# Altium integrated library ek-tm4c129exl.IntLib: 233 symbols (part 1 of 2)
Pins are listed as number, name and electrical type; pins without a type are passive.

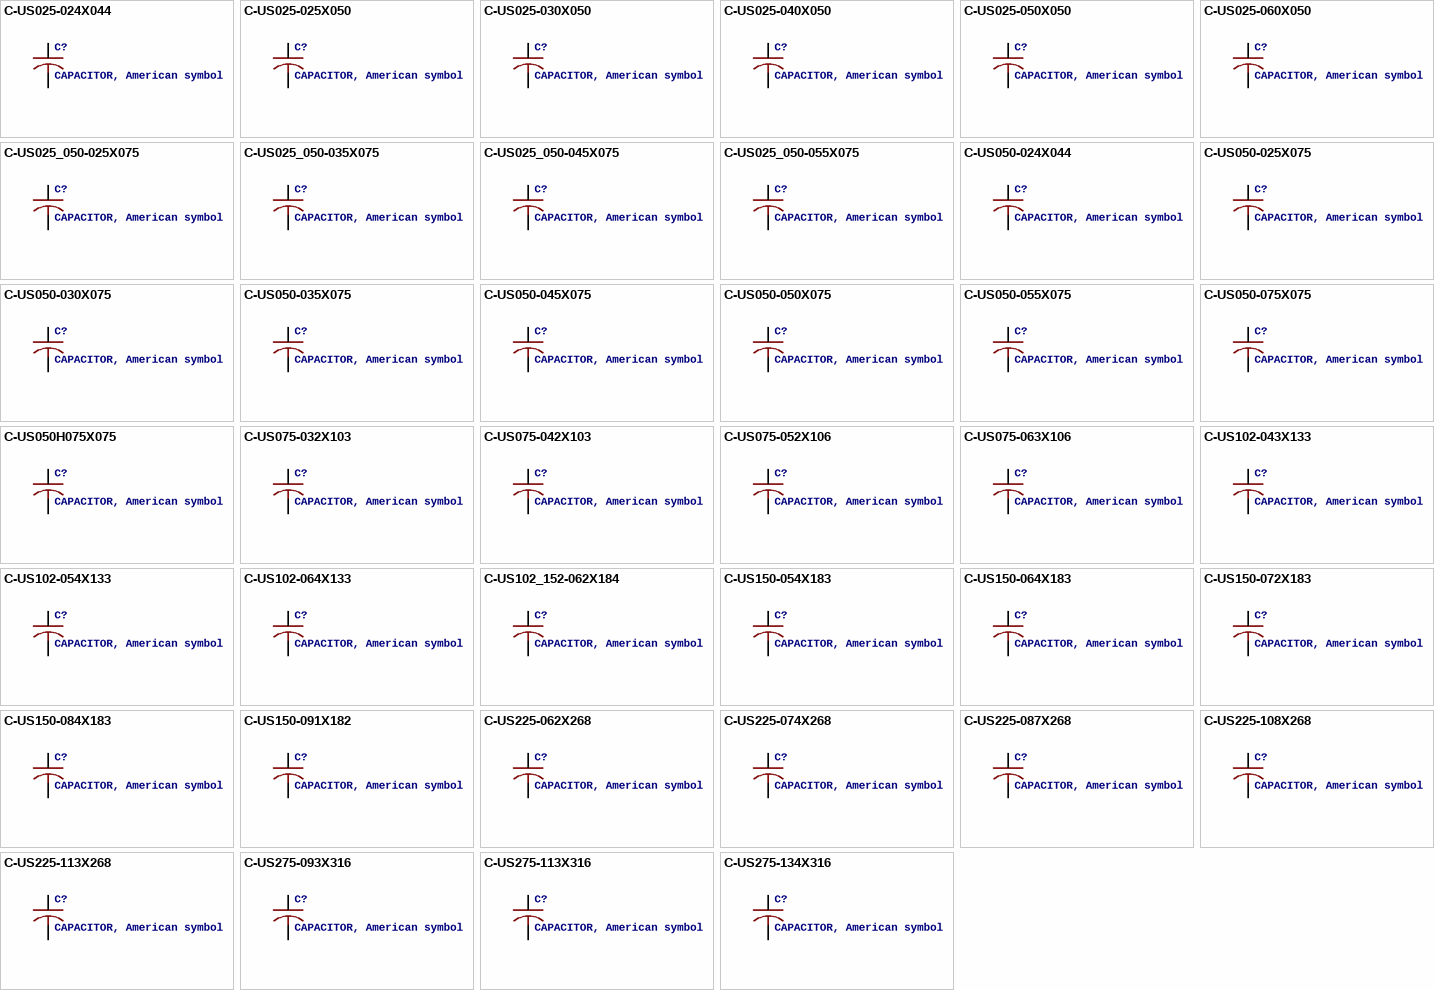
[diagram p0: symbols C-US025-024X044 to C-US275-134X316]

## C-US025-024X044
designator C?, comment CAPACITOR, American symbol
footprint C025-024X044
pins: 1, 2

## C-US025-025X050
designator C?, comment CAPACITOR, American symbol
footprint C025-025X050
pins: 1, 2

## C-US025-030X050
designator C?, comment CAPACITOR, American symbol
footprint C025-030X050
pins: 1, 2

## C-US025-040X050
designator C?, comment CAPACITOR, American symbol
footprint C025-040X050
pins: 1, 2

## C-US025-050X050
designator C?, comment CAPACITOR, American symbol
footprint C025-050X050
pins: 1, 2

## C-US025-060X050
designator C?, comment CAPACITOR, American symbol
footprint C025-060X050
pins: 1, 2

## C-US025_050-025X075
designator C?, comment CAPACITOR, American symbol
footprint C025_050-025X075
pins: 1, 2

## C-US025_050-035X075
designator C?, comment CAPACITOR, American symbol
footprint C025_050-035X075
pins: 1, 2

## C-US025_050-045X075
designator C?, comment CAPACITOR, American symbol
footprint C025_050-045X075
pins: 1, 2

## C-US025_050-055X075
designator C?, comment CAPACITOR, American symbol
footprint C025_050-055X075
pins: 1, 2

## C-US050-024X044
designator C?, comment CAPACITOR, American symbol
footprint C050-024X044
pins: 1, 2

## C-US050-025X075
designator C?, comment CAPACITOR, American symbol
footprint C050-025X075
pins: 1, 2

## C-US050-030X075
designator C?, comment CAPACITOR, American symbol
footprint C050-030X075
pins: 1, 2

## C-US050-035X075
designator C?, comment CAPACITOR, American symbol
footprint C050-035X075
pins: 1, 2

## C-US050-045X075
designator C?, comment CAPACITOR, American symbol
footprint C050-045X075
pins: 1, 2

## C-US050-050X075
designator C?, comment CAPACITOR, American symbol
footprint C050-050X075
pins: 1, 2

## C-US050-055X075
designator C?, comment CAPACITOR, American symbol
footprint C050-055X075
pins: 1, 2

## C-US050-075X075
designator C?, comment CAPACITOR, American symbol
footprint C050-075X075
pins: 1, 2

## C-US050H075X075
designator C?, comment CAPACITOR, American symbol
footprint C050H075X075
pins: 1, 2

## C-US075-032X103
designator C?, comment CAPACITOR, American symbol
footprint C075-032X103
pins: 1, 2

## C-US075-042X103
designator C?, comment CAPACITOR, American symbol
footprint C075-042X103
pins: 1, 2

## C-US075-052X106
designator C?, comment CAPACITOR, American symbol
footprint C075-052X106
pins: 1, 2

## C-US075-063X106
designator C?, comment CAPACITOR, American symbol
footprint C075-063X106
pins: 1, 2

## C-US102-043X133
designator C?, comment CAPACITOR, American symbol
footprint C102-043X133
pins: 1, 2

## C-US102-054X133
designator C?, comment CAPACITOR, American symbol
footprint C102-054X133
pins: 1, 2

## C-US102-064X133
designator C?, comment CAPACITOR, American symbol
footprint C102-064X133
pins: 1, 2

## C-US102_152-062X184
designator C?, comment CAPACITOR, American symbol
footprint C102_152-062X184
pins: 1, 2

## C-US150-054X183
designator C?, comment CAPACITOR, American symbol
footprint C150-054X183
pins: 1, 2

## C-US150-064X183
designator C?, comment CAPACITOR, American symbol
footprint C150-064X183
pins: 1, 2

## C-US150-072X183
designator C?, comment CAPACITOR, American symbol
footprint C150-072X183
pins: 1, 2

## C-US150-084X183
designator C?, comment CAPACITOR, American symbol
footprint C150-084X183
pins: 1, 2

## C-US150-091X182
designator C?, comment CAPACITOR, American symbol
footprint C150-091X182
pins: 1, 2

## C-US225-062X268
designator C?, comment CAPACITOR, American symbol
footprint C225-062X268
pins: 1, 2

## C-US225-074X268
designator C?, comment CAPACITOR, American symbol
footprint C225-074X268
pins: 1, 2

## C-US225-087X268
designator C?, comment CAPACITOR, American symbol
footprint C225-087X268
pins: 1, 2

## C-US225-108X268
designator C?, comment CAPACITOR, American symbol
footprint C225-108X268
pins: 1, 2

## C-US225-113X268
designator C?, comment CAPACITOR, American symbol
footprint C225-113X268
pins: 1, 2

## C-US275-093X316
designator C?, comment CAPACITOR, American symbol
footprint C275-093X316
pins: 1, 2

## C-US275-113X316
designator C?, comment CAPACITOR, American symbol
footprint C275-113X316
pins: 1, 2

## C-US275-134X316
designator C?, comment CAPACITOR, American symbol
footprint C275-134X316
pins: 1, 2

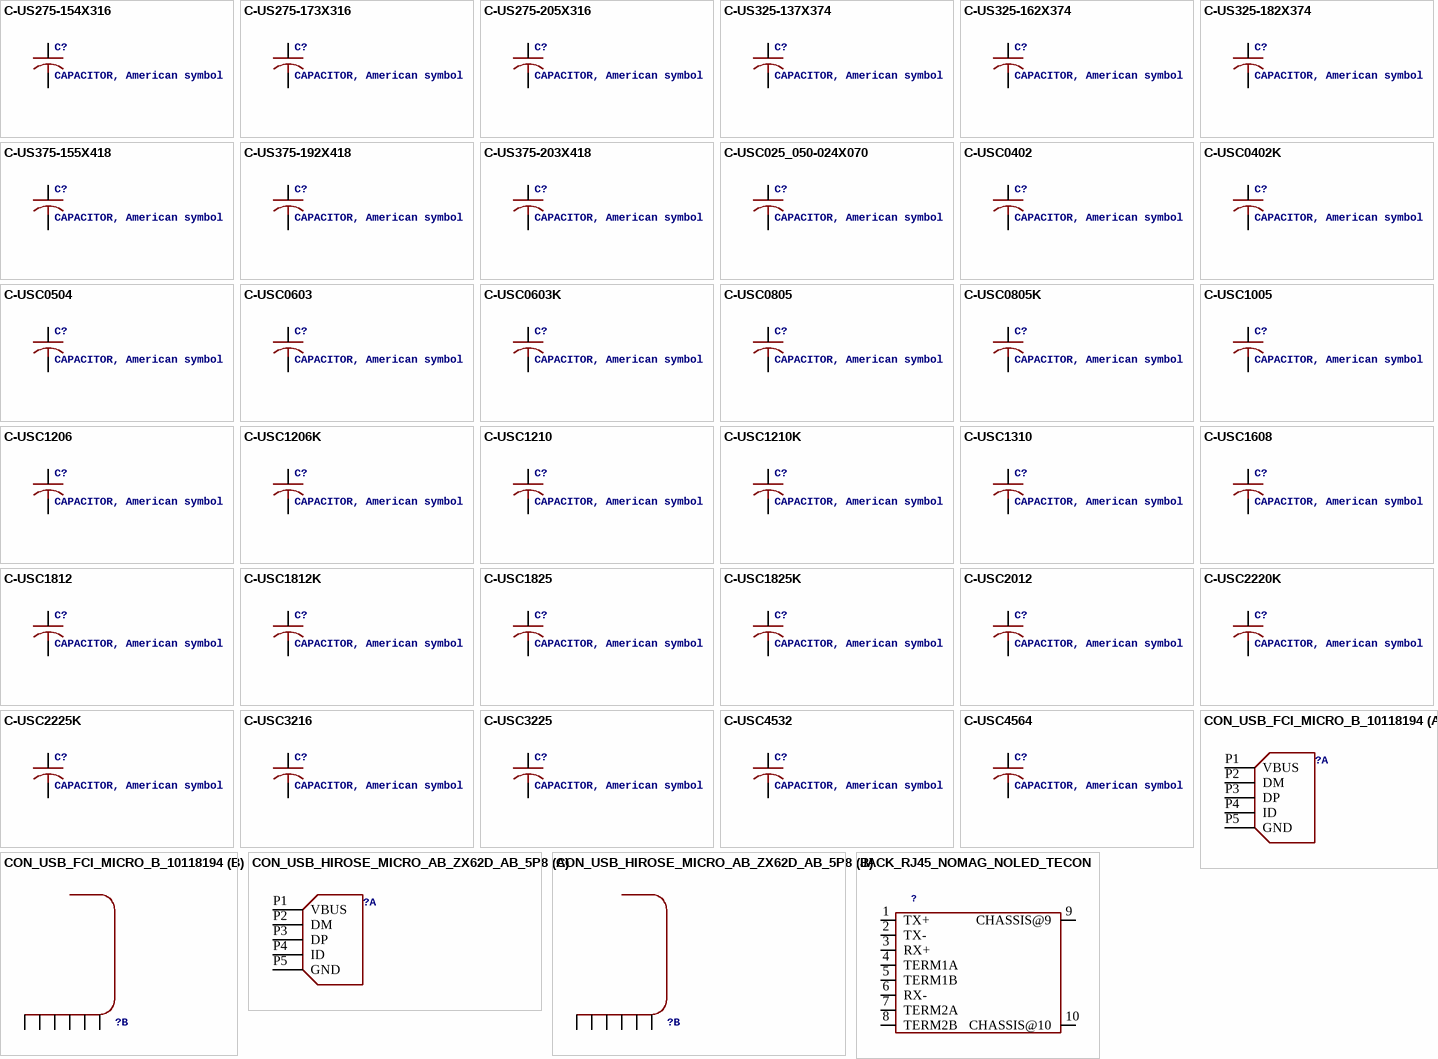
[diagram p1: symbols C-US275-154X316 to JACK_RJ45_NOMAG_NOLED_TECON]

## C-US275-154X316
designator C?, comment CAPACITOR, American symbol
footprint C275-154X316
pins: 1, 2

## C-US275-173X316
designator C?, comment CAPACITOR, American symbol
footprint C275-173X316
pins: 1, 2

## C-US275-205X316
designator C?, comment CAPACITOR, American symbol
footprint C275-205X316
pins: 1, 2

## C-US325-137X374
designator C?, comment CAPACITOR, American symbol
footprint C325-137X374
pins: 1, 2

## C-US325-162X374
designator C?, comment CAPACITOR, American symbol
footprint C325-162X374
pins: 1, 2

## C-US325-182X374
designator C?, comment CAPACITOR, American symbol
footprint C325-182X374
pins: 1, 2

## C-US375-155X418
designator C?, comment CAPACITOR, American symbol
footprint C375-155X418
pins: 1, 2

## C-US375-192X418
designator C?, comment CAPACITOR, American symbol
footprint C375-192X418
pins: 1, 2

## C-US375-203X418
designator C?, comment CAPACITOR, American symbol
footprint C375-203X418
pins: 1, 2

## C-USC025_050-024X070
designator C?, comment CAPACITOR, American symbol
footprint C025_050-024X070
pins: 1, 2

## C-USC0402
designator C?, comment CAPACITOR, American symbol
footprint C0402
pins: 1, 2

## C-USC0402K
designator C?, comment CAPACITOR, American symbol
footprint C0402K
pins: 1, 2

## C-USC0504
designator C?, comment CAPACITOR, American symbol
footprint C0504
pins: 1, 2

## C-USC0603
designator C?, comment CAPACITOR, American symbol
footprint C0603
pins: 1, 2

## C-USC0603K
designator C?, comment CAPACITOR, American symbol
footprint C0603K
pins: 1, 2

## C-USC0805
designator C?, comment CAPACITOR, American symbol
footprint C0805
pins: 1, 2

## C-USC0805K
designator C?, comment CAPACITOR, American symbol
footprint C0805K
pins: 1, 2

## C-USC1005
designator C?, comment CAPACITOR, American symbol
footprint C1005
pins: 1, 2

## C-USC1206
designator C?, comment CAPACITOR, American symbol
footprint C1206
pins: 1, 2

## C-USC1206K
designator C?, comment CAPACITOR, American symbol
footprint C1206K
pins: 1, 2

## C-USC1210
designator C?, comment CAPACITOR, American symbol
footprint C1210
pins: 1, 2

## C-USC1210K
designator C?, comment CAPACITOR, American symbol
footprint C1210K
pins: 1, 2

## C-USC1310
designator C?, comment CAPACITOR, American symbol
footprint C1310
pins: 1, 2

## C-USC1608
designator C?, comment CAPACITOR, American symbol
footprint C1608
pins: 1, 2

## C-USC1812
designator C?, comment CAPACITOR, American symbol
footprint C1812
pins: 1, 2

## C-USC1812K
designator C?, comment CAPACITOR, American symbol
footprint C1812K
pins: 1, 2

## C-USC1825
designator C?, comment CAPACITOR, American symbol
footprint C1825
pins: 1, 2

## C-USC1825K
designator C?, comment CAPACITOR, American symbol
footprint C1825K
pins: 1, 2

## C-USC2012
designator C?, comment CAPACITOR, American symbol
footprint C2012
pins: 1, 2

## C-USC2220K
designator C?, comment CAPACITOR, American symbol
footprint C2220K
pins: 1, 2

## C-USC2225K
designator C?, comment CAPACITOR, American symbol
footprint C2225K
pins: 1, 2

## C-USC3216
designator C?, comment CAPACITOR, American symbol
footprint C3216
pins: 1, 2

## C-USC3225
designator C?, comment CAPACITOR, American symbol
footprint C3225
pins: 1, 2

## C-USC4532
designator C?, comment CAPACITOR, American symbol
footprint C4532
pins: 1, 2

## C-USC4564
designator C?, comment CAPACITOR, American symbol
footprint C4564
pins: 1, 2

## CON_USB_FCI_MICRO_B_10118194
designator ?
footprint CON_USB_MICRO_B_FCI_10118194
part A pins: P1 VBUS, P2 DM, P3 DP, P4 ID, P5 GND
part B pins: P6 S1, P7 S2, P8 S3, P9 S4, P10 S5, P11 S6

## CON_USB_HIROSE_MICRO_AB_ZX62D_AB_5P8
designator ?
footprint CON_USB_MICRO_AB_HIROSE_ZX62D-AB-5P8
part A pins: P1 VBUS, P2 DM, P3 DP, P4 ID, P5 GND
part B pins: P$1 S1, P$2 S2, P$3 S3, P$4 S4, P$5 S5, P$6 S6

## JACK_RJ45_NOMAG_NOLED_TECON
designator ?
footprint RJ45_TE_CON_NOMAG_NOLED
pins: 1 TX+, 2 TX-, 3 RX+, 4 TERM1A, 5 TERM1B, 6 RX-, 7 TERM2A, 8 TERM2B, 9 CHASSIS@9, 10 CHASSIS@10

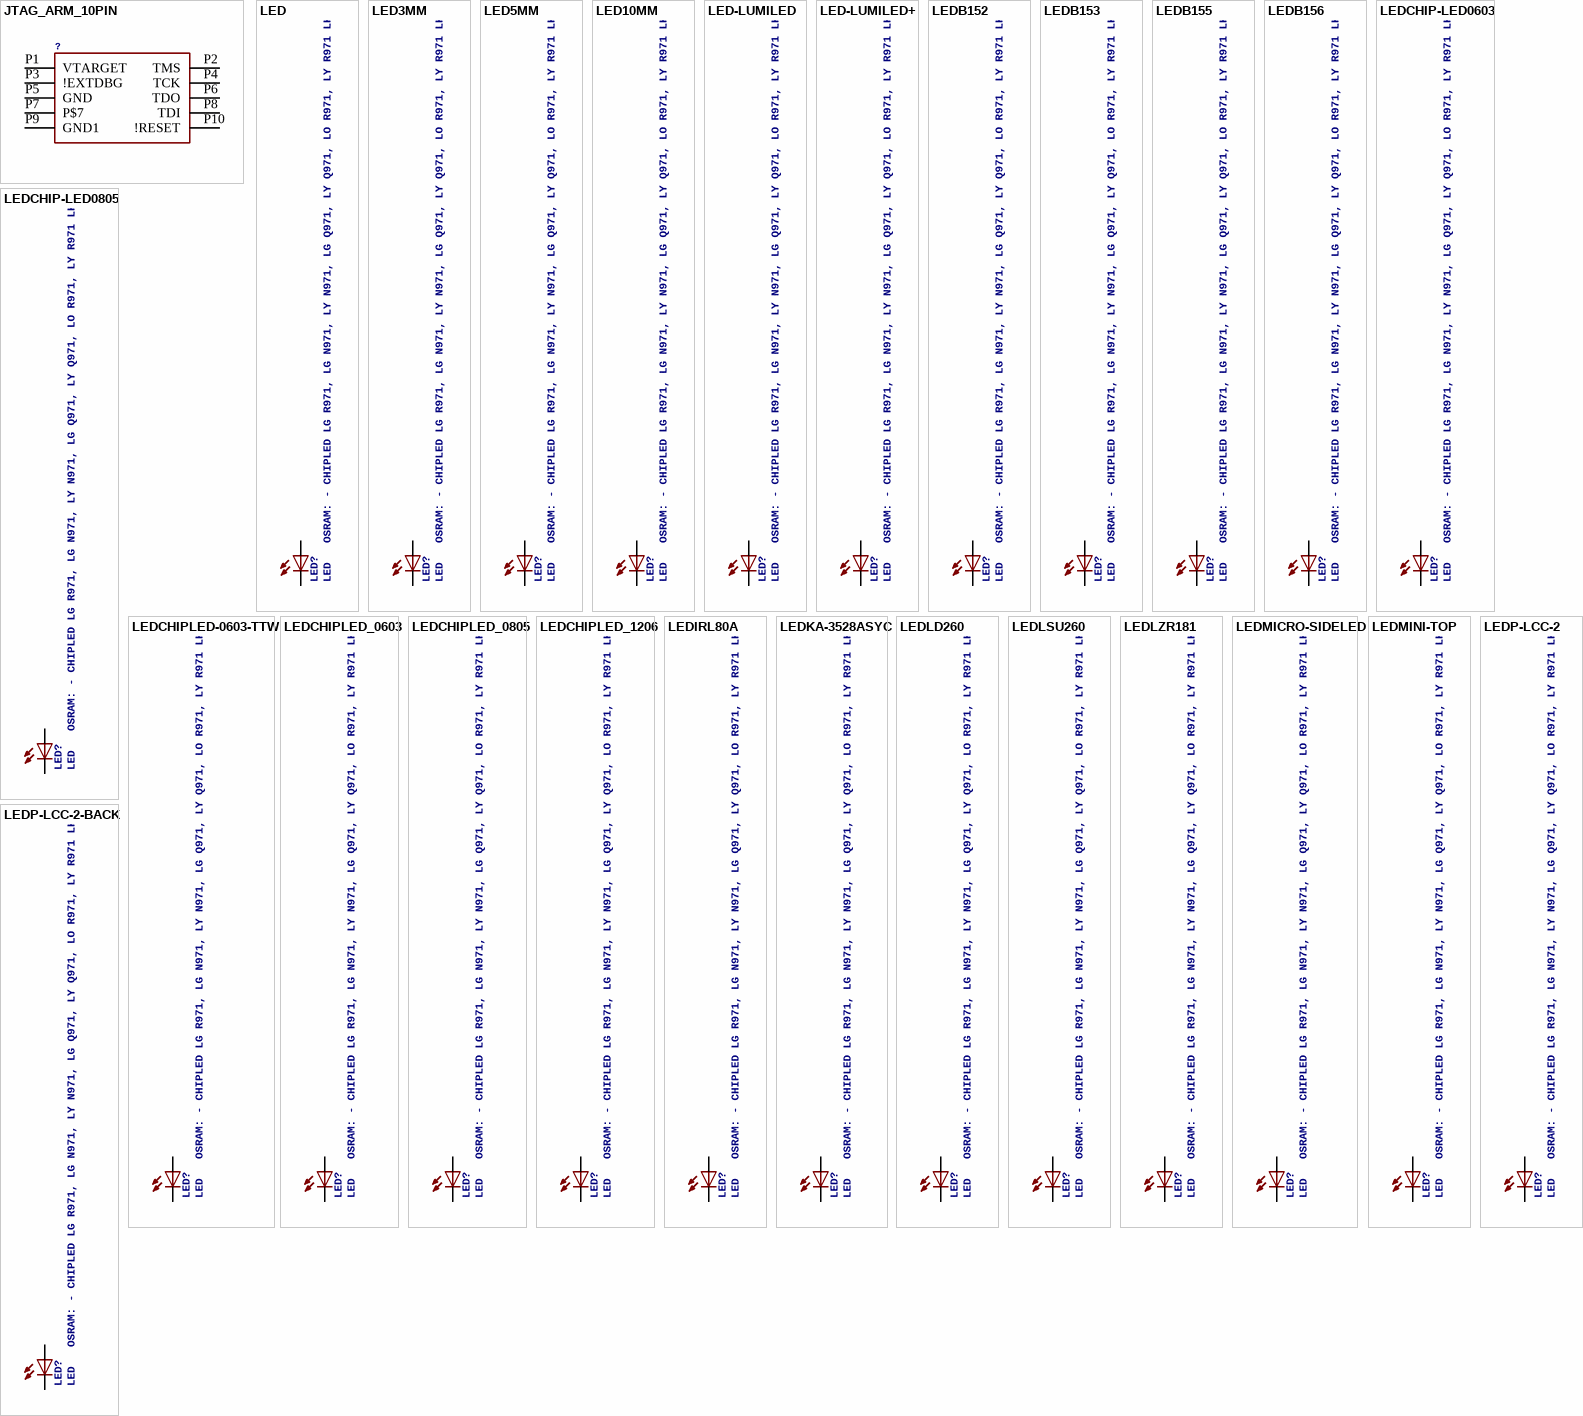
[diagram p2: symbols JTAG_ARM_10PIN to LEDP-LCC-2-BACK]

## JTAG_ARM_10PIN
designator ?
footprint CON_2X5_50MIL
pins: P1 VTARGET, P2 TMS, P3 !EXTDBG, P4 TCK, P5 GND, P6 TDO, P7 P$7, P8 TDI, P9 GND1, P10 !RESET

## LED
designator LED?, comment LED   OSRAM: - CHIPLED LG R971, LG N971, LY N971, LG Q971, LY Q971, LO R971, LY R971 LH N974, LH R974 LS Q976, LO Q976, LY Q976 LO Q996 - Hyper CHIPLED LW Q18S LB Q993, LB Q99A, LB R99A - SideLED LS A670, LO A670, LY A670, LG A670, LP A670 LB A673, LV A673, LT A673, LW A673 LH A674 LY A675 LS A676, LA A676, LO A676, LY A676, LW A676 LS A679, LY A679, LG A679 -  Hyper Micro SIDELEDÂ® LS Y876, LA Y876, LO Y876, LY Y876 LT Y87S - SmartLED LW L88C, LW L88S LB L89C, LB L89S, LG L890 LS L89K, LO L89K, LY L89K LS L896, LA L896, LO L896, LY L896 - TOPLED LS T670, LO T670, LY T670, LG T670, LP T670 LSG T670, LSP T670, LSY T670, LOP T670, LYG T670 LG T671, LOG T671, LSG T671 LB T673, LV T673, LT T673, LW T673 LH T674 LS T676, LA T676, LO T676, LY T676, LB T676, LH T676, LSB T676, LW T676 LB T67C, LV T67C, LT T67C, LS T67K, LO T67K, LY T67K, LW E67C LS E67B, LA E67B, LO E67B, LY E67B, LB E67C, LV E67C, LT E67C LW T67C LS T679, LY T679, LG T679 LS T770, LO T770, LY T770, LG T770, LP T770 LB T773, LV T773, LT T773, LW T773 LH T774 LS E675, LA E675, LY E675, LS T675 LS T776, LA T776, LO T776, LY T776, LB T776 LHGB T686 LT T68C, LB T68C - Hyper Mini TOPLEDÂ® LB M676 - Mini TOPLED SantanaÂ® LG M470 LS M47K, LO M47K, LY M47K    Source: http://www.osram.convergy.de   LUXEON: - LUMILEDÂ® LXK2-PW12-R00, LXK2-PW12-S00, LXK2-PW14-U00, LXK2-PW14-V00 LXK2-PM12-R00, LXK2-PM12-S00, LXK2-PM14-U00 LXK2-PE12-Q00, LXK2-PE12-R00, LXK2-PE12-S00, LXK2-PE14-T00, LXK2-PE14-U00 LXK2-PB12-K00, LXK2-PB12-L00, LXK2-PB12-M00, LXK2-PB14-N00, LXK2-PB14-P00, LXK2-PB14-Q00 LXK2-PR12-L00, LXK2-PR12-M00, LXK2-PR14-Q00, LXK2-PR14-R00 LXK2-PD12-Q00, LXK2-PD12-R00, LXK2-PD12-S00 LXK2-PH12-R00, LXK2-PH12-S00 LXK2-PL12-P00, LXK2-PL12-Q00, LXK2-PL12-R00    Source: www.luxeon.com   KINGBRIGHT:   KA-3528ASYC Source: www.kingbright.com
footprint SMARTLED-TTW
pins: A@1 A, C@1 C

## LED3MM
designator LED?, comment LED   OSRAM: - CHIPLED LG R971, LG N971, LY N971, LG Q971, LY Q971, LO R971, LY R971 LH N974, LH R974 LS Q976, LO Q976, LY Q976 LO Q996 - Hyper CHIPLED LW Q18S LB Q993, LB Q99A, LB R99A - SideLED LS A670, LO A670, LY A670, LG A670, LP A670 LB A673, LV A673, LT A673, LW A673 LH A674 LY A675 LS A676, LA A676, LO A676, LY A676, LW A676 LS A679, LY A679, LG A679 -  Hyper Micro SIDELEDÂ® LS Y876, LA Y876, LO Y876, LY Y876 LT Y87S - SmartLED LW L88C, LW L88S LB L89C, LB L89S, LG L890 LS L89K, LO L89K, LY L89K LS L896, LA L896, LO L896, LY L896 - TOPLED LS T670, LO T670, LY T670, LG T670, LP T670 LSG T670, LSP T670, LSY T670, LOP T670, LYG T670 LG T671, LOG T671, LSG T671 LB T673, LV T673, LT T673, LW T673 LH T674 LS T676, LA T676, LO T676, LY T676, LB T676, LH T676, LSB T676, LW T676 LB T67C, LV T67C, LT T67C, LS T67K, LO T67K, LY T67K, LW E67C LS E67B, LA E67B, LO E67B, LY E67B, LB E67C, LV E67C, LT E67C LW T67C LS T679, LY T679, LG T679 LS T770, LO T770, LY T770, LG T770, LP T770 LB T773, LV T773, LT T773, LW T773 LH T774 LS E675, LA E675, LY E675, LS T675 LS T776, LA T776, LO T776, LY T776, LB T776 LHGB T686 LT T68C, LB T68C - Hyper Mini TOPLEDÂ® LB M676 - Mini TOPLED SantanaÂ® LG M470 LS M47K, LO M47K, LY M47K    Source: http://www.osram.convergy.de   LUXEON: - LUMILEDÂ® LXK2-PW12-R00, LXK2-PW12-S00, LXK2-PW14-U00, LXK2-PW14-V00 LXK2-PM12-R00, LXK2-PM12-S00, LXK2-PM14-U00 LXK2-PE12-Q00, LXK2-PE12-R00, LXK2-PE12-S00, LXK2-PE14-T00, LXK2-PE14-U00 LXK2-PB12-K00, LXK2-PB12-L00, LXK2-PB12-M00, LXK2-PB14-N00, LXK2-PB14-P00, LXK2-PB14-Q00 LXK2-PR12-L00, LXK2-PR12-M00, LXK2-PR14-Q00, LXK2-PR14-R00 LXK2-PD12-Q00, LXK2-PD12-R00, LXK2-PD12-S00 LXK2-PH12-R00, LXK2-PH12-S00 LXK2-PL12-P00, LXK2-PL12-Q00, LXK2-PL12-R00    Source: www.luxeon.com   KINGBRIGHT:   KA-3528ASYC Source: www.kingbright.com
footprint LED3MM
pins: A, K C

## LED5MM
designator LED?, comment LED   OSRAM: - CHIPLED LG R971, LG N971, LY N971, LG Q971, LY Q971, LO R971, LY R971 LH N974, LH R974 LS Q976, LO Q976, LY Q976 LO Q996 - Hyper CHIPLED LW Q18S LB Q993, LB Q99A, LB R99A - SideLED LS A670, LO A670, LY A670, LG A670, LP A670 LB A673, LV A673, LT A673, LW A673 LH A674 LY A675 LS A676, LA A676, LO A676, LY A676, LW A676 LS A679, LY A679, LG A679 -  Hyper Micro SIDELEDÂ® LS Y876, LA Y876, LO Y876, LY Y876 LT Y87S - SmartLED LW L88C, LW L88S LB L89C, LB L89S, LG L890 LS L89K, LO L89K, LY L89K LS L896, LA L896, LO L896, LY L896 - TOPLED LS T670, LO T670, LY T670, LG T670, LP T670 LSG T670, LSP T670, LSY T670, LOP T670, LYG T670 LG T671, LOG T671, LSG T671 LB T673, LV T673, LT T673, LW T673 LH T674 LS T676, LA T676, LO T676, LY T676, LB T676, LH T676, LSB T676, LW T676 LB T67C, LV T67C, LT T67C, LS T67K, LO T67K, LY T67K, LW E67C LS E67B, LA E67B, LO E67B, LY E67B, LB E67C, LV E67C, LT E67C LW T67C LS T679, LY T679, LG T679 LS T770, LO T770, LY T770, LG T770, LP T770 LB T773, LV T773, LT T773, LW T773 LH T774 LS E675, LA E675, LY E675, LS T675 LS T776, LA T776, LO T776, LY T776, LB T776 LHGB T686 LT T68C, LB T68C - Hyper Mini TOPLEDÂ® LB M676 - Mini TOPLED SantanaÂ® LG M470 LS M47K, LO M47K, LY M47K    Source: http://www.osram.convergy.de   LUXEON: - LUMILEDÂ® LXK2-PW12-R00, LXK2-PW12-S00, LXK2-PW14-U00, LXK2-PW14-V00 LXK2-PM12-R00, LXK2-PM12-S00, LXK2-PM14-U00 LXK2-PE12-Q00, LXK2-PE12-R00, LXK2-PE12-S00, LXK2-PE14-T00, LXK2-PE14-U00 LXK2-PB12-K00, LXK2-PB12-L00, LXK2-PB12-M00, LXK2-PB14-N00, LXK2-PB14-P00, LXK2-PB14-Q00 LXK2-PR12-L00, LXK2-PR12-M00, LXK2-PR14-Q00, LXK2-PR14-R00 LXK2-PD12-Q00, LXK2-PD12-R00, LXK2-PD12-S00 LXK2-PH12-R00, LXK2-PH12-S00 LXK2-PL12-P00, LXK2-PL12-Q00, LXK2-PL12-R00    Source: www.luxeon.com   KINGBRIGHT:   KA-3528ASYC Source: www.kingbright.com
footprint LED5MM
pins: A, K C

## LED10MM
designator LED?, comment LED   OSRAM: - CHIPLED LG R971, LG N971, LY N971, LG Q971, LY Q971, LO R971, LY R971 LH N974, LH R974 LS Q976, LO Q976, LY Q976 LO Q996 - Hyper CHIPLED LW Q18S LB Q993, LB Q99A, LB R99A - SideLED LS A670, LO A670, LY A670, LG A670, LP A670 LB A673, LV A673, LT A673, LW A673 LH A674 LY A675 LS A676, LA A676, LO A676, LY A676, LW A676 LS A679, LY A679, LG A679 -  Hyper Micro SIDELEDÂ® LS Y876, LA Y876, LO Y876, LY Y876 LT Y87S - SmartLED LW L88C, LW L88S LB L89C, LB L89S, LG L890 LS L89K, LO L89K, LY L89K LS L896, LA L896, LO L896, LY L896 - TOPLED LS T670, LO T670, LY T670, LG T670, LP T670 LSG T670, LSP T670, LSY T670, LOP T670, LYG T670 LG T671, LOG T671, LSG T671 LB T673, LV T673, LT T673, LW T673 LH T674 LS T676, LA T676, LO T676, LY T676, LB T676, LH T676, LSB T676, LW T676 LB T67C, LV T67C, LT T67C, LS T67K, LO T67K, LY T67K, LW E67C LS E67B, LA E67B, LO E67B, LY E67B, LB E67C, LV E67C, LT E67C LW T67C LS T679, LY T679, LG T679 LS T770, LO T770, LY T770, LG T770, LP T770 LB T773, LV T773, LT T773, LW T773 LH T774 LS E675, LA E675, LY E675, LS T675 LS T776, LA T776, LO T776, LY T776, LB T776 LHGB T686 LT T68C, LB T68C - Hyper Mini TOPLEDÂ® LB M676 - Mini TOPLED SantanaÂ® LG M470 LS M47K, LO M47K, LY M47K    Source: http://www.osram.convergy.de   LUXEON: - LUMILEDÂ® LXK2-PW12-R00, LXK2-PW12-S00, LXK2-PW14-U00, LXK2-PW14-V00 LXK2-PM12-R00, LXK2-PM12-S00, LXK2-PM14-U00 LXK2-PE12-Q00, LXK2-PE12-R00, LXK2-PE12-S00, LXK2-PE14-T00, LXK2-PE14-U00 LXK2-PB12-K00, LXK2-PB12-L00, LXK2-PB12-M00, LXK2-PB14-N00, LXK2-PB14-P00, LXK2-PB14-Q00 LXK2-PR12-L00, LXK2-PR12-M00, LXK2-PR14-Q00, LXK2-PR14-R00 LXK2-PD12-Q00, LXK2-PD12-R00, LXK2-PD12-S00 LXK2-PH12-R00, LXK2-PH12-S00 LXK2-PL12-P00, LXK2-PL12-Q00, LXK2-PL12-R00    Source: www.luxeon.com   KINGBRIGHT:   KA-3528ASYC Source: www.kingbright.com
footprint LED10MM
pins: A, K C

## LED-LUMILED
designator LED?, comment LED   OSRAM: - CHIPLED LG R971, LG N971, LY N971, LG Q971, LY Q971, LO R971, LY R971 LH N974, LH R974 LS Q976, LO Q976, LY Q976 LO Q996 - Hyper CHIPLED LW Q18S LB Q993, LB Q99A, LB R99A - SideLED LS A670, LO A670, LY A670, LG A670, LP A670 LB A673, LV A673, LT A673, LW A673 LH A674 LY A675 LS A676, LA A676, LO A676, LY A676, LW A676 LS A679, LY A679, LG A679 -  Hyper Micro SIDELEDÂ® LS Y876, LA Y876, LO Y876, LY Y876 LT Y87S - SmartLED LW L88C, LW L88S LB L89C, LB L89S, LG L890 LS L89K, LO L89K, LY L89K LS L896, LA L896, LO L896, LY L896 - TOPLED LS T670, LO T670, LY T670, LG T670, LP T670 LSG T670, LSP T670, LSY T670, LOP T670, LYG T670 LG T671, LOG T671, LSG T671 LB T673, LV T673, LT T673, LW T673 LH T674 LS T676, LA T676, LO T676, LY T676, LB T676, LH T676, LSB T676, LW T676 LB T67C, LV T67C, LT T67C, LS T67K, LO T67K, LY T67K, LW E67C LS E67B, LA E67B, LO E67B, LY E67B, LB E67C, LV E67C, LT E67C LW T67C LS T679, LY T679, LG T679 LS T770, LO T770, LY T770, LG T770, LP T770 LB T773, LV T773, LT T773, LW T773 LH T774 LS E675, LA E675, LY E675, LS T675 LS T776, LA T776, LO T776, LY T776, LB T776 LHGB T686 LT T68C, LB T68C - Hyper Mini TOPLEDÂ® LB M676 - Mini TOPLED SantanaÂ® LG M470 LS M47K, LO M47K, LY M47K    Source: http://www.osram.convergy.de   LUXEON: - LUMILEDÂ® LXK2-PW12-R00, LXK2-PW12-S00, LXK2-PW14-U00, LXK2-PW14-V00 LXK2-PM12-R00, LXK2-PM12-S00, LXK2-PM14-U00 LXK2-PE12-Q00, LXK2-PE12-R00, LXK2-PE12-S00, LXK2-PE14-T00, LXK2-PE14-U00 LXK2-PB12-K00, LXK2-PB12-L00, LXK2-PB12-M00, LXK2-PB14-N00, LXK2-PB14-P00, LXK2-PB14-Q00 LXK2-PR12-L00, LXK2-PR12-M00, LXK2-PR14-Q00, LXK2-PR14-R00 LXK2-PD12-Q00, LXK2-PD12-R00, LXK2-PD12-S00 LXK2-PH12-R00, LXK2-PH12-S00 LXK2-PL12-P00, LXK2-PL12-Q00, LXK2-PL12-R00    Source: www.luxeon.com   KINGBRIGHT:   KA-3528ASYC Source: www.kingbright.com
footprint LUMILED
pins: 2+ A, 4- C

## LED-LUMILED+
designator LED?, comment LED   OSRAM: - CHIPLED LG R971, LG N971, LY N971, LG Q971, LY Q971, LO R971, LY R971 LH N974, LH R974 LS Q976, LO Q976, LY Q976 LO Q996 - Hyper CHIPLED LW Q18S LB Q993, LB Q99A, LB R99A - SideLED LS A670, LO A670, LY A670, LG A670, LP A670 LB A673, LV A673, LT A673, LW A673 LH A674 LY A675 LS A676, LA A676, LO A676, LY A676, LW A676 LS A679, LY A679, LG A679 -  Hyper Micro SIDELEDÂ® LS Y876, LA Y876, LO Y876, LY Y876 LT Y87S - SmartLED LW L88C, LW L88S LB L89C, LB L89S, LG L890 LS L89K, LO L89K, LY L89K LS L896, LA L896, LO L896, LY L896 - TOPLED LS T670, LO T670, LY T670, LG T670, LP T670 LSG T670, LSP T670, LSY T670, LOP T670, LYG T670 LG T671, LOG T671, LSG T671 LB T673, LV T673, LT T673, LW T673 LH T674 LS T676, LA T676, LO T676, LY T676, LB T676, LH T676, LSB T676, LW T676 LB T67C, LV T67C, LT T67C, LS T67K, LO T67K, LY T67K, LW E67C LS E67B, LA E67B, LO E67B, LY E67B, LB E67C, LV E67C, LT E67C LW T67C LS T679, LY T679, LG T679 LS T770, LO T770, LY T770, LG T770, LP T770 LB T773, LV T773, LT T773, LW T773 LH T774 LS E675, LA E675, LY E675, LS T675 LS T776, LA T776, LO T776, LY T776, LB T776 LHGB T686 LT T68C, LB T68C - Hyper Mini TOPLEDÂ® LB M676 - Mini TOPLED SantanaÂ® LG M470 LS M47K, LO M47K, LY M47K    Source: http://www.osram.convergy.de   LUXEON: - LUMILEDÂ® LXK2-PW12-R00, LXK2-PW12-S00, LXK2-PW14-U00, LXK2-PW14-V00 LXK2-PM12-R00, LXK2-PM12-S00, LXK2-PM14-U00 LXK2-PE12-Q00, LXK2-PE12-R00, LXK2-PE12-S00, LXK2-PE14-T00, LXK2-PE14-U00 LXK2-PB12-K00, LXK2-PB12-L00, LXK2-PB12-M00, LXK2-PB14-N00, LXK2-PB14-P00, LXK2-PB14-Q00 LXK2-PR12-L00, LXK2-PR12-M00, LXK2-PR14-Q00, LXK2-PR14-R00 LXK2-PD12-Q00, LXK2-PD12-R00, LXK2-PD12-S00 LXK2-PH12-R00, LXK2-PH12-S00 LXK2-PL12-P00, LXK2-PL12-Q00, LXK2-PL12-R00    Source: www.luxeon.com   KINGBRIGHT:   KA-3528ASYC Source: www.kingbright.com
footprint LUMILED+
pins: 2+ A, 4- C

## LEDB152
designator LED?, comment LED   OSRAM: - CHIPLED LG R971, LG N971, LY N971, LG Q971, LY Q971, LO R971, LY R971 LH N974, LH R974 LS Q976, LO Q976, LY Q976 LO Q996 - Hyper CHIPLED LW Q18S LB Q993, LB Q99A, LB R99A - SideLED LS A670, LO A670, LY A670, LG A670, LP A670 LB A673, LV A673, LT A673, LW A673 LH A674 LY A675 LS A676, LA A676, LO A676, LY A676, LW A676 LS A679, LY A679, LG A679 -  Hyper Micro SIDELEDÂ® LS Y876, LA Y876, LO Y876, LY Y876 LT Y87S - SmartLED LW L88C, LW L88S LB L89C, LB L89S, LG L890 LS L89K, LO L89K, LY L89K LS L896, LA L896, LO L896, LY L896 - TOPLED LS T670, LO T670, LY T670, LG T670, LP T670 LSG T670, LSP T670, LSY T670, LOP T670, LYG T670 LG T671, LOG T671, LSG T671 LB T673, LV T673, LT T673, LW T673 LH T674 LS T676, LA T676, LO T676, LY T676, LB T676, LH T676, LSB T676, LW T676 LB T67C, LV T67C, LT T67C, LS T67K, LO T67K, LY T67K, LW E67C LS E67B, LA E67B, LO E67B, LY E67B, LB E67C, LV E67C, LT E67C LW T67C LS T679, LY T679, LG T679 LS T770, LO T770, LY T770, LG T770, LP T770 LB T773, LV T773, LT T773, LW T773 LH T774 LS E675, LA E675, LY E675, LS T675 LS T776, LA T776, LO T776, LY T776, LB T776 LHGB T686 LT T68C, LB T68C - Hyper Mini TOPLEDÂ® LB M676 - Mini TOPLED SantanaÂ® LG M470 LS M47K, LO M47K, LY M47K    Source: http://www.osram.convergy.de   LUXEON: - LUMILEDÂ® LXK2-PW12-R00, LXK2-PW12-S00, LXK2-PW14-U00, LXK2-PW14-V00 LXK2-PM12-R00, LXK2-PM12-S00, LXK2-PM14-U00 LXK2-PE12-Q00, LXK2-PE12-R00, LXK2-PE12-S00, LXK2-PE14-T00, LXK2-PE14-U00 LXK2-PB12-K00, LXK2-PB12-L00, LXK2-PB12-M00, LXK2-PB14-N00, LXK2-PB14-P00, LXK2-PB14-Q00 LXK2-PR12-L00, LXK2-PR12-M00, LXK2-PR14-Q00, LXK2-PR14-R00 LXK2-PD12-Q00, LXK2-PD12-R00, LXK2-PD12-S00 LXK2-PH12-R00, LXK2-PH12-S00 LXK2-PL12-P00, LXK2-PL12-Q00, LXK2-PL12-R00    Source: www.luxeon.com   KINGBRIGHT:   KA-3528ASYC Source: www.kingbright.com
footprint Q62902-B152
pins: A, K C

## LEDB153
designator LED?, comment LED   OSRAM: - CHIPLED LG R971, LG N971, LY N971, LG Q971, LY Q971, LO R971, LY R971 LH N974, LH R974 LS Q976, LO Q976, LY Q976 LO Q996 - Hyper CHIPLED LW Q18S LB Q993, LB Q99A, LB R99A - SideLED LS A670, LO A670, LY A670, LG A670, LP A670 LB A673, LV A673, LT A673, LW A673 LH A674 LY A675 LS A676, LA A676, LO A676, LY A676, LW A676 LS A679, LY A679, LG A679 -  Hyper Micro SIDELEDÂ® LS Y876, LA Y876, LO Y876, LY Y876 LT Y87S - SmartLED LW L88C, LW L88S LB L89C, LB L89S, LG L890 LS L89K, LO L89K, LY L89K LS L896, LA L896, LO L896, LY L896 - TOPLED LS T670, LO T670, LY T670, LG T670, LP T670 LSG T670, LSP T670, LSY T670, LOP T670, LYG T670 LG T671, LOG T671, LSG T671 LB T673, LV T673, LT T673, LW T673 LH T674 LS T676, LA T676, LO T676, LY T676, LB T676, LH T676, LSB T676, LW T676 LB T67C, LV T67C, LT T67C, LS T67K, LO T67K, LY T67K, LW E67C LS E67B, LA E67B, LO E67B, LY E67B, LB E67C, LV E67C, LT E67C LW T67C LS T679, LY T679, LG T679 LS T770, LO T770, LY T770, LG T770, LP T770 LB T773, LV T773, LT T773, LW T773 LH T774 LS E675, LA E675, LY E675, LS T675 LS T776, LA T776, LO T776, LY T776, LB T776 LHGB T686 LT T68C, LB T68C - Hyper Mini TOPLEDÂ® LB M676 - Mini TOPLED SantanaÂ® LG M470 LS M47K, LO M47K, LY M47K    Source: http://www.osram.convergy.de   LUXEON: - LUMILEDÂ® LXK2-PW12-R00, LXK2-PW12-S00, LXK2-PW14-U00, LXK2-PW14-V00 LXK2-PM12-R00, LXK2-PM12-S00, LXK2-PM14-U00 LXK2-PE12-Q00, LXK2-PE12-R00, LXK2-PE12-S00, LXK2-PE14-T00, LXK2-PE14-U00 LXK2-PB12-K00, LXK2-PB12-L00, LXK2-PB12-M00, LXK2-PB14-N00, LXK2-PB14-P00, LXK2-PB14-Q00 LXK2-PR12-L00, LXK2-PR12-M00, LXK2-PR14-Q00, LXK2-PR14-R00 LXK2-PD12-Q00, LXK2-PD12-R00, LXK2-PD12-S00 LXK2-PH12-R00, LXK2-PH12-S00 LXK2-PL12-P00, LXK2-PL12-Q00, LXK2-PL12-R00    Source: www.luxeon.com   KINGBRIGHT:   KA-3528ASYC Source: www.kingbright.com
footprint Q62902-B153
pins: A, K C

## LEDB155
designator LED?, comment LED   OSRAM: - CHIPLED LG R971, LG N971, LY N971, LG Q971, LY Q971, LO R971, LY R971 LH N974, LH R974 LS Q976, LO Q976, LY Q976 LO Q996 - Hyper CHIPLED LW Q18S LB Q993, LB Q99A, LB R99A - SideLED LS A670, LO A670, LY A670, LG A670, LP A670 LB A673, LV A673, LT A673, LW A673 LH A674 LY A675 LS A676, LA A676, LO A676, LY A676, LW A676 LS A679, LY A679, LG A679 -  Hyper Micro SIDELEDÂ® LS Y876, LA Y876, LO Y876, LY Y876 LT Y87S - SmartLED LW L88C, LW L88S LB L89C, LB L89S, LG L890 LS L89K, LO L89K, LY L89K LS L896, LA L896, LO L896, LY L896 - TOPLED LS T670, LO T670, LY T670, LG T670, LP T670 LSG T670, LSP T670, LSY T670, LOP T670, LYG T670 LG T671, LOG T671, LSG T671 LB T673, LV T673, LT T673, LW T673 LH T674 LS T676, LA T676, LO T676, LY T676, LB T676, LH T676, LSB T676, LW T676 LB T67C, LV T67C, LT T67C, LS T67K, LO T67K, LY T67K, LW E67C LS E67B, LA E67B, LO E67B, LY E67B, LB E67C, LV E67C, LT E67C LW T67C LS T679, LY T679, LG T679 LS T770, LO T770, LY T770, LG T770, LP T770 LB T773, LV T773, LT T773, LW T773 LH T774 LS E675, LA E675, LY E675, LS T675 LS T776, LA T776, LO T776, LY T776, LB T776 LHGB T686 LT T68C, LB T68C - Hyper Mini TOPLEDÂ® LB M676 - Mini TOPLED SantanaÂ® LG M470 LS M47K, LO M47K, LY M47K    Source: http://www.osram.convergy.de   LUXEON: - LUMILEDÂ® LXK2-PW12-R00, LXK2-PW12-S00, LXK2-PW14-U00, LXK2-PW14-V00 LXK2-PM12-R00, LXK2-PM12-S00, LXK2-PM14-U00 LXK2-PE12-Q00, LXK2-PE12-R00, LXK2-PE12-S00, LXK2-PE14-T00, LXK2-PE14-U00 LXK2-PB12-K00, LXK2-PB12-L00, LXK2-PB12-M00, LXK2-PB14-N00, LXK2-PB14-P00, LXK2-PB14-Q00 LXK2-PR12-L00, LXK2-PR12-M00, LXK2-PR14-Q00, LXK2-PR14-R00 LXK2-PD12-Q00, LXK2-PD12-R00, LXK2-PD12-S00 LXK2-PH12-R00, LXK2-PH12-S00 LXK2-PL12-P00, LXK2-PL12-Q00, LXK2-PL12-R00    Source: www.luxeon.com   KINGBRIGHT:   KA-3528ASYC Source: www.kingbright.com
footprint Q62902-B155
pins: A, K C

## LEDB156
designator LED?, comment LED   OSRAM: - CHIPLED LG R971, LG N971, LY N971, LG Q971, LY Q971, LO R971, LY R971 LH N974, LH R974 LS Q976, LO Q976, LY Q976 LO Q996 - Hyper CHIPLED LW Q18S LB Q993, LB Q99A, LB R99A - SideLED LS A670, LO A670, LY A670, LG A670, LP A670 LB A673, LV A673, LT A673, LW A673 LH A674 LY A675 LS A676, LA A676, LO A676, LY A676, LW A676 LS A679, LY A679, LG A679 -  Hyper Micro SIDELEDÂ® LS Y876, LA Y876, LO Y876, LY Y876 LT Y87S - SmartLED LW L88C, LW L88S LB L89C, LB L89S, LG L890 LS L89K, LO L89K, LY L89K LS L896, LA L896, LO L896, LY L896 - TOPLED LS T670, LO T670, LY T670, LG T670, LP T670 LSG T670, LSP T670, LSY T670, LOP T670, LYG T670 LG T671, LOG T671, LSG T671 LB T673, LV T673, LT T673, LW T673 LH T674 LS T676, LA T676, LO T676, LY T676, LB T676, LH T676, LSB T676, LW T676 LB T67C, LV T67C, LT T67C, LS T67K, LO T67K, LY T67K, LW E67C LS E67B, LA E67B, LO E67B, LY E67B, LB E67C, LV E67C, LT E67C LW T67C LS T679, LY T679, LG T679 LS T770, LO T770, LY T770, LG T770, LP T770 LB T773, LV T773, LT T773, LW T773 LH T774 LS E675, LA E675, LY E675, LS T675 LS T776, LA T776, LO T776, LY T776, LB T776 LHGB T686 LT T68C, LB T68C - Hyper Mini TOPLEDÂ® LB M676 - Mini TOPLED SantanaÂ® LG M470 LS M47K, LO M47K, LY M47K    Source: http://www.osram.convergy.de   LUXEON: - LUMILEDÂ® LXK2-PW12-R00, LXK2-PW12-S00, LXK2-PW14-U00, LXK2-PW14-V00 LXK2-PM12-R00, LXK2-PM12-S00, LXK2-PM14-U00 LXK2-PE12-Q00, LXK2-PE12-R00, LXK2-PE12-S00, LXK2-PE14-T00, LXK2-PE14-U00 LXK2-PB12-K00, LXK2-PB12-L00, LXK2-PB12-M00, LXK2-PB14-N00, LXK2-PB14-P00, LXK2-PB14-Q00 LXK2-PR12-L00, LXK2-PR12-M00, LXK2-PR14-Q00, LXK2-PR14-R00 LXK2-PD12-Q00, LXK2-PD12-R00, LXK2-PD12-S00 LXK2-PH12-R00, LXK2-PH12-S00 LXK2-PL12-P00, LXK2-PL12-Q00, LXK2-PL12-R00    Source: www.luxeon.com   KINGBRIGHT:   KA-3528ASYC Source: www.kingbright.com
footprint Q62902-B156
pins: A, K C

## LEDCHIP-LED0603
designator LED?, comment LED   OSRAM: - CHIPLED LG R971, LG N971, LY N971, LG Q971, LY Q971, LO R971, LY R971 LH N974, LH R974 LS Q976, LO Q976, LY Q976 LO Q996 - Hyper CHIPLED LW Q18S LB Q993, LB Q99A, LB R99A - SideLED LS A670, LO A670, LY A670, LG A670, LP A670 LB A673, LV A673, LT A673, LW A673 LH A674 LY A675 LS A676, LA A676, LO A676, LY A676, LW A676 LS A679, LY A679, LG A679 -  Hyper Micro SIDELEDÂ® LS Y876, LA Y876, LO Y876, LY Y876 LT Y87S - SmartLED LW L88C, LW L88S LB L89C, LB L89S, LG L890 LS L89K, LO L89K, LY L89K LS L896, LA L896, LO L896, LY L896 - TOPLED LS T670, LO T670, LY T670, LG T670, LP T670 LSG T670, LSP T670, LSY T670, LOP T670, LYG T670 LG T671, LOG T671, LSG T671 LB T673, LV T673, LT T673, LW T673 LH T674 LS T676, LA T676, LO T676, LY T676, LB T676, LH T676, LSB T676, LW T676 LB T67C, LV T67C, LT T67C, LS T67K, LO T67K, LY T67K, LW E67C LS E67B, LA E67B, LO E67B, LY E67B, LB E67C, LV E67C, LT E67C LW T67C LS T679, LY T679, LG T679 LS T770, LO T770, LY T770, LG T770, LP T770 LB T773, LV T773, LT T773, LW T773 LH T774 LS E675, LA E675, LY E675, LS T675 LS T776, LA T776, LO T776, LY T776, LB T776 LHGB T686 LT T68C, LB T68C - Hyper Mini TOPLEDÂ® LB M676 - Mini TOPLED SantanaÂ® LG M470 LS M47K, LO M47K, LY M47K    Source: http://www.osram.convergy.de   LUXEON: - LUMILEDÂ® LXK2-PW12-R00, LXK2-PW12-S00, LXK2-PW14-U00, LXK2-PW14-V00 LXK2-PM12-R00, LXK2-PM12-S00, LXK2-PM14-U00 LXK2-PE12-Q00, LXK2-PE12-R00, LXK2-PE12-S00, LXK2-PE14-T00, LXK2-PE14-U00 LXK2-PB12-K00, LXK2-PB12-L00, LXK2-PB12-M00, LXK2-PB14-N00, LXK2-PB14-P00, LXK2-PB14-Q00 LXK2-PR12-L00, LXK2-PR12-M00, LXK2-PR14-Q00, LXK2-PR14-R00 LXK2-PD12-Q00, LXK2-PD12-R00, LXK2-PD12-S00 LXK2-PH12-R00, LXK2-PH12-S00 LXK2-PL12-P00, LXK2-PL12-Q00, LXK2-PL12-R00    Source: www.luxeon.com   KINGBRIGHT:   KA-3528ASYC Source: www.kingbright.com
footprint CHIP-LED0603
pins: A, C

## LEDCHIP-LED0805
designator LED?, comment LED   OSRAM: - CHIPLED LG R971, LG N971, LY N971, LG Q971, LY Q971, LO R971, LY R971 LH N974, LH R974 LS Q976, LO Q976, LY Q976 LO Q996 - Hyper CHIPLED LW Q18S LB Q993, LB Q99A, LB R99A - SideLED LS A670, LO A670, LY A670, LG A670, LP A670 LB A673, LV A673, LT A673, LW A673 LH A674 LY A675 LS A676, LA A676, LO A676, LY A676, LW A676 LS A679, LY A679, LG A679 -  Hyper Micro SIDELEDÂ® LS Y876, LA Y876, LO Y876, LY Y876 LT Y87S - SmartLED LW L88C, LW L88S LB L89C, LB L89S, LG L890 LS L89K, LO L89K, LY L89K LS L896, LA L896, LO L896, LY L896 - TOPLED LS T670, LO T670, LY T670, LG T670, LP T670 LSG T670, LSP T670, LSY T670, LOP T670, LYG T670 LG T671, LOG T671, LSG T671 LB T673, LV T673, LT T673, LW T673 LH T674 LS T676, LA T676, LO T676, LY T676, LB T676, LH T676, LSB T676, LW T676 LB T67C, LV T67C, LT T67C, LS T67K, LO T67K, LY T67K, LW E67C LS E67B, LA E67B, LO E67B, LY E67B, LB E67C, LV E67C, LT E67C LW T67C LS T679, LY T679, LG T679 LS T770, LO T770, LY T770, LG T770, LP T770 LB T773, LV T773, LT T773, LW T773 LH T774 LS E675, LA E675, LY E675, LS T675 LS T776, LA T776, LO T776, LY T776, LB T776 LHGB T686 LT T68C, LB T68C - Hyper Mini TOPLEDÂ® LB M676 - Mini TOPLED SantanaÂ® LG M470 LS M47K, LO M47K, LY M47K    Source: http://www.osram.convergy.de   LUXEON: - LUMILEDÂ® LXK2-PW12-R00, LXK2-PW12-S00, LXK2-PW14-U00, LXK2-PW14-V00 LXK2-PM12-R00, LXK2-PM12-S00, LXK2-PM14-U00 LXK2-PE12-Q00, LXK2-PE12-R00, LXK2-PE12-S00, LXK2-PE14-T00, LXK2-PE14-U00 LXK2-PB12-K00, LXK2-PB12-L00, LXK2-PB12-M00, LXK2-PB14-N00, LXK2-PB14-P00, LXK2-PB14-Q00 LXK2-PR12-L00, LXK2-PR12-M00, LXK2-PR14-Q00, LXK2-PR14-R00 LXK2-PD12-Q00, LXK2-PD12-R00, LXK2-PD12-S00 LXK2-PH12-R00, LXK2-PH12-S00 LXK2-PL12-P00, LXK2-PL12-Q00, LXK2-PL12-R00    Source: www.luxeon.com   KINGBRIGHT:   KA-3528ASYC Source: www.kingbright.com
footprint CHIP-LED0805
pins: A, C

## LEDCHIPLED-0603-TTW
designator LED?, comment LED   OSRAM: - CHIPLED LG R971, LG N971, LY N971, LG Q971, LY Q971, LO R971, LY R971 LH N974, LH R974 LS Q976, LO Q976, LY Q976 LO Q996 - Hyper CHIPLED LW Q18S LB Q993, LB Q99A, LB R99A - SideLED LS A670, LO A670, LY A670, LG A670, LP A670 LB A673, LV A673, LT A673, LW A673 LH A674 LY A675 LS A676, LA A676, LO A676, LY A676, LW A676 LS A679, LY A679, LG A679 -  Hyper Micro SIDELEDÂ® LS Y876, LA Y876, LO Y876, LY Y876 LT Y87S - SmartLED LW L88C, LW L88S LB L89C, LB L89S, LG L890 LS L89K, LO L89K, LY L89K LS L896, LA L896, LO L896, LY L896 - TOPLED LS T670, LO T670, LY T670, LG T670, LP T670 LSG T670, LSP T670, LSY T670, LOP T670, LYG T670 LG T671, LOG T671, LSG T671 LB T673, LV T673, LT T673, LW T673 LH T674 LS T676, LA T676, LO T676, LY T676, LB T676, LH T676, LSB T676, LW T676 LB T67C, LV T67C, LT T67C, LS T67K, LO T67K, LY T67K, LW E67C LS E67B, LA E67B, LO E67B, LY E67B, LB E67C, LV E67C, LT E67C LW T67C LS T679, LY T679, LG T679 LS T770, LO T770, LY T770, LG T770, LP T770 LB T773, LV T773, LT T773, LW T773 LH T774 LS E675, LA E675, LY E675, LS T675 LS T776, LA T776, LO T776, LY T776, LB T776 LHGB T686 LT T68C, LB T68C - Hyper Mini TOPLEDÂ® LB M676 - Mini TOPLED SantanaÂ® LG M470 LS M47K, LO M47K, LY M47K    Source: http://www.osram.convergy.de   LUXEON: - LUMILEDÂ® LXK2-PW12-R00, LXK2-PW12-S00, LXK2-PW14-U00, LXK2-PW14-V00 LXK2-PM12-R00, LXK2-PM12-S00, LXK2-PM14-U00 LXK2-PE12-Q00, LXK2-PE12-R00, LXK2-PE12-S00, LXK2-PE14-T00, LXK2-PE14-U00 LXK2-PB12-K00, LXK2-PB12-L00, LXK2-PB12-M00, LXK2-PB14-N00, LXK2-PB14-P00, LXK2-PB14-Q00 LXK2-PR12-L00, LXK2-PR12-M00, LXK2-PR14-Q00, LXK2-PR14-R00 LXK2-PD12-Q00, LXK2-PD12-R00, LXK2-PD12-S00 LXK2-PH12-R00, LXK2-PH12-S00 LXK2-PL12-P00, LXK2-PL12-Q00, LXK2-PL12-R00    Source: www.luxeon.com   KINGBRIGHT:   KA-3528ASYC Source: www.kingbright.com
footprint CHIPLED-0603-TTW
pins: A@1 A, C@1 C

## LEDCHIPLED_0603
designator LED?, comment LED   OSRAM: - CHIPLED LG R971, LG N971, LY N971, LG Q971, LY Q971, LO R971, LY R971 LH N974, LH R974 LS Q976, LO Q976, LY Q976 LO Q996 - Hyper CHIPLED LW Q18S LB Q993, LB Q99A, LB R99A - SideLED LS A670, LO A670, LY A670, LG A670, LP A670 LB A673, LV A673, LT A673, LW A673 LH A674 LY A675 LS A676, LA A676, LO A676, LY A676, LW A676 LS A679, LY A679, LG A679 -  Hyper Micro SIDELEDÂ® LS Y876, LA Y876, LO Y876, LY Y876 LT Y87S - SmartLED LW L88C, LW L88S LB L89C, LB L89S, LG L890 LS L89K, LO L89K, LY L89K LS L896, LA L896, LO L896, LY L896 - TOPLED LS T670, LO T670, LY T670, LG T670, LP T670 LSG T670, LSP T670, LSY T670, LOP T670, LYG T670 LG T671, LOG T671, LSG T671 LB T673, LV T673, LT T673, LW T673 LH T674 LS T676, LA T676, LO T676, LY T676, LB T676, LH T676, LSB T676, LW T676 LB T67C, LV T67C, LT T67C, LS T67K, LO T67K, LY T67K, LW E67C LS E67B, LA E67B, LO E67B, LY E67B, LB E67C, LV E67C, LT E67C LW T67C LS T679, LY T679, LG T679 LS T770, LO T770, LY T770, LG T770, LP T770 LB T773, LV T773, LT T773, LW T773 LH T774 LS E675, LA E675, LY E675, LS T675 LS T776, LA T776, LO T776, LY T776, LB T776 LHGB T686 LT T68C, LB T68C - Hyper Mini TOPLEDÂ® LB M676 - Mini TOPLED SantanaÂ® LG M470 LS M47K, LO M47K, LY M47K    Source: http://www.osram.convergy.de   LUXEON: - LUMILEDÂ® LXK2-PW12-R00, LXK2-PW12-S00, LXK2-PW14-U00, LXK2-PW14-V00 LXK2-PM12-R00, LXK2-PM12-S00, LXK2-PM14-U00 LXK2-PE12-Q00, LXK2-PE12-R00, LXK2-PE12-S00, LXK2-PE14-T00, LXK2-PE14-U00 LXK2-PB12-K00, LXK2-PB12-L00, LXK2-PB12-M00, LXK2-PB14-N00, LXK2-PB14-P00, LXK2-PB14-Q00 LXK2-PR12-L00, LXK2-PR12-M00, LXK2-PR14-Q00, LXK2-PR14-R00 LXK2-PD12-Q00, LXK2-PD12-R00, LXK2-PD12-S00 LXK2-PH12-R00, LXK2-PH12-S00 LXK2-PL12-P00, LXK2-PL12-Q00, LXK2-PL12-R00    Source: www.luxeon.com   KINGBRIGHT:   KA-3528ASYC Source: www.kingbright.com
footprint CHIPLED_0603
pins: A, C

## LEDCHIPLED_0805
designator LED?, comment LED   OSRAM: - CHIPLED LG R971, LG N971, LY N971, LG Q971, LY Q971, LO R971, LY R971 LH N974, LH R974 LS Q976, LO Q976, LY Q976 LO Q996 - Hyper CHIPLED LW Q18S LB Q993, LB Q99A, LB R99A - SideLED LS A670, LO A670, LY A670, LG A670, LP A670 LB A673, LV A673, LT A673, LW A673 LH A674 LY A675 LS A676, LA A676, LO A676, LY A676, LW A676 LS A679, LY A679, LG A679 -  Hyper Micro SIDELEDÂ® LS Y876, LA Y876, LO Y876, LY Y876 LT Y87S - SmartLED LW L88C, LW L88S LB L89C, LB L89S, LG L890 LS L89K, LO L89K, LY L89K LS L896, LA L896, LO L896, LY L896 - TOPLED LS T670, LO T670, LY T670, LG T670, LP T670 LSG T670, LSP T670, LSY T670, LOP T670, LYG T670 LG T671, LOG T671, LSG T671 LB T673, LV T673, LT T673, LW T673 LH T674 LS T676, LA T676, LO T676, LY T676, LB T676, LH T676, LSB T676, LW T676 LB T67C, LV T67C, LT T67C, LS T67K, LO T67K, LY T67K, LW E67C LS E67B, LA E67B, LO E67B, LY E67B, LB E67C, LV E67C, LT E67C LW T67C LS T679, LY T679, LG T679 LS T770, LO T770, LY T770, LG T770, LP T770 LB T773, LV T773, LT T773, LW T773 LH T774 LS E675, LA E675, LY E675, LS T675 LS T776, LA T776, LO T776, LY T776, LB T776 LHGB T686 LT T68C, LB T68C - Hyper Mini TOPLEDÂ® LB M676 - Mini TOPLED SantanaÂ® LG M470 LS M47K, LO M47K, LY M47K    Source: http://www.osram.convergy.de   LUXEON: - LUMILEDÂ® LXK2-PW12-R00, LXK2-PW12-S00, LXK2-PW14-U00, LXK2-PW14-V00 LXK2-PM12-R00, LXK2-PM12-S00, LXK2-PM14-U00 LXK2-PE12-Q00, LXK2-PE12-R00, LXK2-PE12-S00, LXK2-PE14-T00, LXK2-PE14-U00 LXK2-PB12-K00, LXK2-PB12-L00, LXK2-PB12-M00, LXK2-PB14-N00, LXK2-PB14-P00, LXK2-PB14-Q00 LXK2-PR12-L00, LXK2-PR12-M00, LXK2-PR14-Q00, LXK2-PR14-R00 LXK2-PD12-Q00, LXK2-PD12-R00, LXK2-PD12-S00 LXK2-PH12-R00, LXK2-PH12-S00 LXK2-PL12-P00, LXK2-PL12-Q00, LXK2-PL12-R00    Source: www.luxeon.com   KINGBRIGHT:   KA-3528ASYC Source: www.kingbright.com
footprint CHIPLED_0805
pins: A, C

## LEDCHIPLED_1206
designator LED?, comment LED   OSRAM: - CHIPLED LG R971, LG N971, LY N971, LG Q971, LY Q971, LO R971, LY R971 LH N974, LH R974 LS Q976, LO Q976, LY Q976 LO Q996 - Hyper CHIPLED LW Q18S LB Q993, LB Q99A, LB R99A - SideLED LS A670, LO A670, LY A670, LG A670, LP A670 LB A673, LV A673, LT A673, LW A673 LH A674 LY A675 LS A676, LA A676, LO A676, LY A676, LW A676 LS A679, LY A679, LG A679 -  Hyper Micro SIDELEDÂ® LS Y876, LA Y876, LO Y876, LY Y876 LT Y87S - SmartLED LW L88C, LW L88S LB L89C, LB L89S, LG L890 LS L89K, LO L89K, LY L89K LS L896, LA L896, LO L896, LY L896 - TOPLED LS T670, LO T670, LY T670, LG T670, LP T670 LSG T670, LSP T670, LSY T670, LOP T670, LYG T670 LG T671, LOG T671, LSG T671 LB T673, LV T673, LT T673, LW T673 LH T674 LS T676, LA T676, LO T676, LY T676, LB T676, LH T676, LSB T676, LW T676 LB T67C, LV T67C, LT T67C, LS T67K, LO T67K, LY T67K, LW E67C LS E67B, LA E67B, LO E67B, LY E67B, LB E67C, LV E67C, LT E67C LW T67C LS T679, LY T679, LG T679 LS T770, LO T770, LY T770, LG T770, LP T770 LB T773, LV T773, LT T773, LW T773 LH T774 LS E675, LA E675, LY E675, LS T675 LS T776, LA T776, LO T776, LY T776, LB T776 LHGB T686 LT T68C, LB T68C - Hyper Mini TOPLEDÂ® LB M676 - Mini TOPLED SantanaÂ® LG M470 LS M47K, LO M47K, LY M47K    Source: http://www.osram.convergy.de   LUXEON: - LUMILEDÂ® LXK2-PW12-R00, LXK2-PW12-S00, LXK2-PW14-U00, LXK2-PW14-V00 LXK2-PM12-R00, LXK2-PM12-S00, LXK2-PM14-U00 LXK2-PE12-Q00, LXK2-PE12-R00, LXK2-PE12-S00, LXK2-PE14-T00, LXK2-PE14-U00 LXK2-PB12-K00, LXK2-PB12-L00, LXK2-PB12-M00, LXK2-PB14-N00, LXK2-PB14-P00, LXK2-PB14-Q00 LXK2-PR12-L00, LXK2-PR12-M00, LXK2-PR14-Q00, LXK2-PR14-R00 LXK2-PD12-Q00, LXK2-PD12-R00, LXK2-PD12-S00 LXK2-PH12-R00, LXK2-PH12-S00 LXK2-PL12-P00, LXK2-PL12-Q00, LXK2-PL12-R00    Source: www.luxeon.com   KINGBRIGHT:   KA-3528ASYC Source: www.kingbright.com
footprint CHIPLED_1206
pins: A, C

## LEDIRL80A
designator LED?, comment LED   OSRAM: - CHIPLED LG R971, LG N971, LY N971, LG Q971, LY Q971, LO R971, LY R971 LH N974, LH R974 LS Q976, LO Q976, LY Q976 LO Q996 - Hyper CHIPLED LW Q18S LB Q993, LB Q99A, LB R99A - SideLED LS A670, LO A670, LY A670, LG A670, LP A670 LB A673, LV A673, LT A673, LW A673 LH A674 LY A675 LS A676, LA A676, LO A676, LY A676, LW A676 LS A679, LY A679, LG A679 -  Hyper Micro SIDELEDÂ® LS Y876, LA Y876, LO Y876, LY Y876 LT Y87S - SmartLED LW L88C, LW L88S LB L89C, LB L89S, LG L890 LS L89K, LO L89K, LY L89K LS L896, LA L896, LO L896, LY L896 - TOPLED LS T670, LO T670, LY T670, LG T670, LP T670 LSG T670, LSP T670, LSY T670, LOP T670, LYG T670 LG T671, LOG T671, LSG T671 LB T673, LV T673, LT T673, LW T673 LH T674 LS T676, LA T676, LO T676, LY T676, LB T676, LH T676, LSB T676, LW T676 LB T67C, LV T67C, LT T67C, LS T67K, LO T67K, LY T67K, LW E67C LS E67B, LA E67B, LO E67B, LY E67B, LB E67C, LV E67C, LT E67C LW T67C LS T679, LY T679, LG T679 LS T770, LO T770, LY T770, LG T770, LP T770 LB T773, LV T773, LT T773, LW T773 LH T774 LS E675, LA E675, LY E675, LS T675 LS T776, LA T776, LO T776, LY T776, LB T776 LHGB T686 LT T68C, LB T68C - Hyper Mini TOPLEDÂ® LB M676 - Mini TOPLED SantanaÂ® LG M470 LS M47K, LO M47K, LY M47K    Source: http://www.osram.convergy.de   LUXEON: - LUMILEDÂ® LXK2-PW12-R00, LXK2-PW12-S00, LXK2-PW14-U00, LXK2-PW14-V00 LXK2-PM12-R00, LXK2-PM12-S00, LXK2-PM14-U00 LXK2-PE12-Q00, LXK2-PE12-R00, LXK2-PE12-S00, LXK2-PE14-T00, LXK2-PE14-U00 LXK2-PB12-K00, LXK2-PB12-L00, LXK2-PB12-M00, LXK2-PB14-N00, LXK2-PB14-P00, LXK2-PB14-Q00 LXK2-PR12-L00, LXK2-PR12-M00, LXK2-PR14-Q00, LXK2-PR14-R00 LXK2-PD12-Q00, LXK2-PD12-R00, LXK2-PD12-S00 LXK2-PH12-R00, LXK2-PH12-S00 LXK2-PL12-P00, LXK2-PL12-Q00, LXK2-PL12-R00    Source: www.luxeon.com   KINGBRIGHT:   KA-3528ASYC Source: www.kingbright.com
footprint IRL80A
pins: A, K C

## LEDKA-3528ASYC
designator LED?, comment LED   OSRAM: - CHIPLED LG R971, LG N971, LY N971, LG Q971, LY Q971, LO R971, LY R971 LH N974, LH R974 LS Q976, LO Q976, LY Q976 LO Q996 - Hyper CHIPLED LW Q18S LB Q993, LB Q99A, LB R99A - SideLED LS A670, LO A670, LY A670, LG A670, LP A670 LB A673, LV A673, LT A673, LW A673 LH A674 LY A675 LS A676, LA A676, LO A676, LY A676, LW A676 LS A679, LY A679, LG A679 -  Hyper Micro SIDELEDÂ® LS Y876, LA Y876, LO Y876, LY Y876 LT Y87S - SmartLED LW L88C, LW L88S LB L89C, LB L89S, LG L890 LS L89K, LO L89K, LY L89K LS L896, LA L896, LO L896, LY L896 - TOPLED LS T670, LO T670, LY T670, LG T670, LP T670 LSG T670, LSP T670, LSY T670, LOP T670, LYG T670 LG T671, LOG T671, LSG T671 LB T673, LV T673, LT T673, LW T673 LH T674 LS T676, LA T676, LO T676, LY T676, LB T676, LH T676, LSB T676, LW T676 LB T67C, LV T67C, LT T67C, LS T67K, LO T67K, LY T67K, LW E67C LS E67B, LA E67B, LO E67B, LY E67B, LB E67C, LV E67C, LT E67C LW T67C LS T679, LY T679, LG T679 LS T770, LO T770, LY T770, LG T770, LP T770 LB T773, LV T773, LT T773, LW T773 LH T774 LS E675, LA E675, LY E675, LS T675 LS T776, LA T776, LO T776, LY T776, LB T776 LHGB T686 LT T68C, LB T68C - Hyper Mini TOPLEDÂ® LB M676 - Mini TOPLED SantanaÂ® LG M470 LS M47K, LO M47K, LY M47K    Source: http://www.osram.convergy.de   LUXEON: - LUMILEDÂ® LXK2-PW12-R00, LXK2-PW12-S00, LXK2-PW14-U00, LXK2-PW14-V00 LXK2-PM12-R00, LXK2-PM12-S00, LXK2-PM14-U00 LXK2-PE12-Q00, LXK2-PE12-R00, LXK2-PE12-S00, LXK2-PE14-T00, LXK2-PE14-U00 LXK2-PB12-K00, LXK2-PB12-L00, LXK2-PB12-M00, LXK2-PB14-N00, LXK2-PB14-P00, LXK2-PB14-Q00 LXK2-PR12-L00, LXK2-PR12-M00, LXK2-PR14-Q00, LXK2-PR14-R00 LXK2-PD12-Q00, LXK2-PD12-R00, LXK2-PD12-S00 LXK2-PH12-R00, LXK2-PH12-S00 LXK2-PL12-P00, LXK2-PL12-Q00, LXK2-PL12-R00    Source: www.luxeon.com   KINGBRIGHT:   KA-3528ASYC Source: www.kingbright.com
footprint KA-3528ASYC
pins: A, C

## LEDLD260
designator LED?, comment LED   OSRAM: - CHIPLED LG R971, LG N971, LY N971, LG Q971, LY Q971, LO R971, LY R971 LH N974, LH R974 LS Q976, LO Q976, LY Q976 LO Q996 - Hyper CHIPLED LW Q18S LB Q993, LB Q99A, LB R99A - SideLED LS A670, LO A670, LY A670, LG A670, LP A670 LB A673, LV A673, LT A673, LW A673 LH A674 LY A675 LS A676, LA A676, LO A676, LY A676, LW A676 LS A679, LY A679, LG A679 -  Hyper Micro SIDELEDÂ® LS Y876, LA Y876, LO Y876, LY Y876 LT Y87S - SmartLED LW L88C, LW L88S LB L89C, LB L89S, LG L890 LS L89K, LO L89K, LY L89K LS L896, LA L896, LO L896, LY L896 - TOPLED LS T670, LO T670, LY T670, LG T670, LP T670 LSG T670, LSP T670, LSY T670, LOP T670, LYG T670 LG T671, LOG T671, LSG T671 LB T673, LV T673, LT T673, LW T673 LH T674 LS T676, LA T676, LO T676, LY T676, LB T676, LH T676, LSB T676, LW T676 LB T67C, LV T67C, LT T67C, LS T67K, LO T67K, LY T67K, LW E67C LS E67B, LA E67B, LO E67B, LY E67B, LB E67C, LV E67C, LT E67C LW T67C LS T679, LY T679, LG T679 LS T770, LO T770, LY T770, LG T770, LP T770 LB T773, LV T773, LT T773, LW T773 LH T774 LS E675, LA E675, LY E675, LS T675 LS T776, LA T776, LO T776, LY T776, LB T776 LHGB T686 LT T68C, LB T68C - Hyper Mini TOPLEDÂ® LB M676 - Mini TOPLED SantanaÂ® LG M470 LS M47K, LO M47K, LY M47K    Source: http://www.osram.convergy.de   LUXEON: - LUMILEDÂ® LXK2-PW12-R00, LXK2-PW12-S00, LXK2-PW14-U00, LXK2-PW14-V00 LXK2-PM12-R00, LXK2-PM12-S00, LXK2-PM14-U00 LXK2-PE12-Q00, LXK2-PE12-R00, LXK2-PE12-S00, LXK2-PE14-T00, LXK2-PE14-U00 LXK2-PB12-K00, LXK2-PB12-L00, LXK2-PB12-M00, LXK2-PB14-N00, LXK2-PB14-P00, LXK2-PB14-Q00 LXK2-PR12-L00, LXK2-PR12-M00, LXK2-PR14-Q00, LXK2-PR14-R00 LXK2-PD12-Q00, LXK2-PD12-R00, LXK2-PD12-S00 LXK2-PH12-R00, LXK2-PH12-S00 LXK2-PL12-P00, LXK2-PL12-Q00, LXK2-PL12-R00    Source: www.luxeon.com   KINGBRIGHT:   KA-3528ASYC Source: www.kingbright.com
footprint LD260
pins: A, K C

## LEDLSU260
designator LED?, comment LED   OSRAM: - CHIPLED LG R971, LG N971, LY N971, LG Q971, LY Q971, LO R971, LY R971 LH N974, LH R974 LS Q976, LO Q976, LY Q976 LO Q996 - Hyper CHIPLED LW Q18S LB Q993, LB Q99A, LB R99A - SideLED LS A670, LO A670, LY A670, LG A670, LP A670 LB A673, LV A673, LT A673, LW A673 LH A674 LY A675 LS A676, LA A676, LO A676, LY A676, LW A676 LS A679, LY A679, LG A679 -  Hyper Micro SIDELEDÂ® LS Y876, LA Y876, LO Y876, LY Y876 LT Y87S - SmartLED LW L88C, LW L88S LB L89C, LB L89S, LG L890 LS L89K, LO L89K, LY L89K LS L896, LA L896, LO L896, LY L896 - TOPLED LS T670, LO T670, LY T670, LG T670, LP T670 LSG T670, LSP T670, LSY T670, LOP T670, LYG T670 LG T671, LOG T671, LSG T671 LB T673, LV T673, LT T673, LW T673 LH T674 LS T676, LA T676, LO T676, LY T676, LB T676, LH T676, LSB T676, LW T676 LB T67C, LV T67C, LT T67C, LS T67K, LO T67K, LY T67K, LW E67C LS E67B, LA E67B, LO E67B, LY E67B, LB E67C, LV E67C, LT E67C LW T67C LS T679, LY T679, LG T679 LS T770, LO T770, LY T770, LG T770, LP T770 LB T773, LV T773, LT T773, LW T773 LH T774 LS E675, LA E675, LY E675, LS T675 LS T776, LA T776, LO T776, LY T776, LB T776 LHGB T686 LT T68C, LB T68C - Hyper Mini TOPLEDÂ® LB M676 - Mini TOPLED SantanaÂ® LG M470 LS M47K, LO M47K, LY M47K    Source: http://www.osram.convergy.de   LUXEON: - LUMILEDÂ® LXK2-PW12-R00, LXK2-PW12-S00, LXK2-PW14-U00, LXK2-PW14-V00 LXK2-PM12-R00, LXK2-PM12-S00, LXK2-PM14-U00 LXK2-PE12-Q00, LXK2-PE12-R00, LXK2-PE12-S00, LXK2-PE14-T00, LXK2-PE14-U00 LXK2-PB12-K00, LXK2-PB12-L00, LXK2-PB12-M00, LXK2-PB14-N00, LXK2-PB14-P00, LXK2-PB14-Q00 LXK2-PR12-L00, LXK2-PR12-M00, LXK2-PR14-Q00, LXK2-PR14-R00 LXK2-PD12-Q00, LXK2-PD12-R00, LXK2-PD12-S00 LXK2-PH12-R00, LXK2-PH12-S00 LXK2-PL12-P00, LXK2-PL12-Q00, LXK2-PL12-R00    Source: www.luxeon.com   KINGBRIGHT:   KA-3528ASYC Source: www.kingbright.com
footprint LSU260
pins: A, K C

## LEDLZR181
designator LED?, comment LED   OSRAM: - CHIPLED LG R971, LG N971, LY N971, LG Q971, LY Q971, LO R971, LY R971 LH N974, LH R974 LS Q976, LO Q976, LY Q976 LO Q996 - Hyper CHIPLED LW Q18S LB Q993, LB Q99A, LB R99A - SideLED LS A670, LO A670, LY A670, LG A670, LP A670 LB A673, LV A673, LT A673, LW A673 LH A674 LY A675 LS A676, LA A676, LO A676, LY A676, LW A676 LS A679, LY A679, LG A679 -  Hyper Micro SIDELEDÂ® LS Y876, LA Y876, LO Y876, LY Y876 LT Y87S - SmartLED LW L88C, LW L88S LB L89C, LB L89S, LG L890 LS L89K, LO L89K, LY L89K LS L896, LA L896, LO L896, LY L896 - TOPLED LS T670, LO T670, LY T670, LG T670, LP T670 LSG T670, LSP T670, LSY T670, LOP T670, LYG T670 LG T671, LOG T671, LSG T671 LB T673, LV T673, LT T673, LW T673 LH T674 LS T676, LA T676, LO T676, LY T676, LB T676, LH T676, LSB T676, LW T676 LB T67C, LV T67C, LT T67C, LS T67K, LO T67K, LY T67K, LW E67C LS E67B, LA E67B, LO E67B, LY E67B, LB E67C, LV E67C, LT E67C LW T67C LS T679, LY T679, LG T679 LS T770, LO T770, LY T770, LG T770, LP T770 LB T773, LV T773, LT T773, LW T773 LH T774 LS E675, LA E675, LY E675, LS T675 LS T776, LA T776, LO T776, LY T776, LB T776 LHGB T686 LT T68C, LB T68C - Hyper Mini TOPLEDÂ® LB M676 - Mini TOPLED SantanaÂ® LG M470 LS M47K, LO M47K, LY M47K    Source: http://www.osram.convergy.de   LUXEON: - LUMILEDÂ® LXK2-PW12-R00, LXK2-PW12-S00, LXK2-PW14-U00, LXK2-PW14-V00 LXK2-PM12-R00, LXK2-PM12-S00, LXK2-PM14-U00 LXK2-PE12-Q00, LXK2-PE12-R00, LXK2-PE12-S00, LXK2-PE14-T00, LXK2-PE14-U00 LXK2-PB12-K00, LXK2-PB12-L00, LXK2-PB12-M00, LXK2-PB14-N00, LXK2-PB14-P00, LXK2-PB14-Q00 LXK2-PR12-L00, LXK2-PR12-M00, LXK2-PR14-Q00, LXK2-PR14-R00 LXK2-PD12-Q00, LXK2-PD12-R00, LXK2-PD12-S00 LXK2-PH12-R00, LXK2-PH12-S00 LXK2-PL12-P00, LXK2-PL12-Q00, LXK2-PL12-R00    Source: www.luxeon.com   KINGBRIGHT:   KA-3528ASYC Source: www.kingbright.com
footprint LZR181
pins: A, K C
